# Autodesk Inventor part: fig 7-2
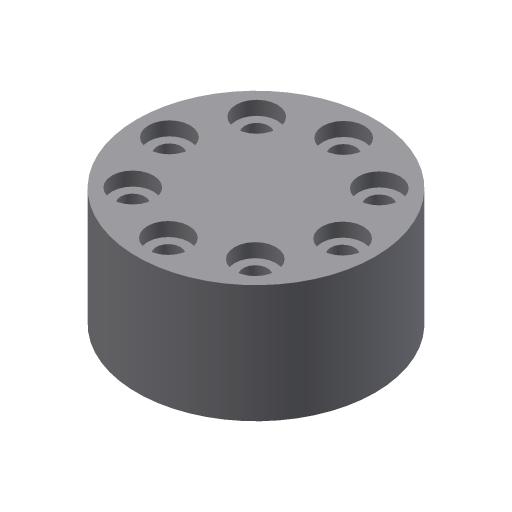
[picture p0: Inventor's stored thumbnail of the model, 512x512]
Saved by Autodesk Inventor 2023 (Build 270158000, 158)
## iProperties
Created: 2004-05
Part Number: fig 7-2
Document SubType Name: Modeling
Designer: CADCIM Technologies
Manufacturer: Standard
Standards Organization: Custom
Density: 1 g/cm^3
Material: Generic
Appearance: Default
Author: CADCIM Technologies
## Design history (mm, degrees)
sketch "Sketch1"
  geometry: C1 r 17.175 at (0, 0)
  constraints: 1 centre point
extrude "Extrusion1" new body sketch "Sketch1" distance "d0" = 17; taper "d1" = 0 deg
sketch "Sketch2"
  geometry: 1 further point
hole "Hole1" sketch "Sketch2" at (12.571, -0.074) diameter "d2" = 3.5; stored, may be unused: countersink angle "d6" = 90 deg, drill point angle "d8" = 118 deg; dims "d3" = 6, "d4" = 6, "d5" = 2, "d7" = 8
pattern_circular "Circular Pattern1" dims angle "d11" = 360 deg
body "Solid1"
